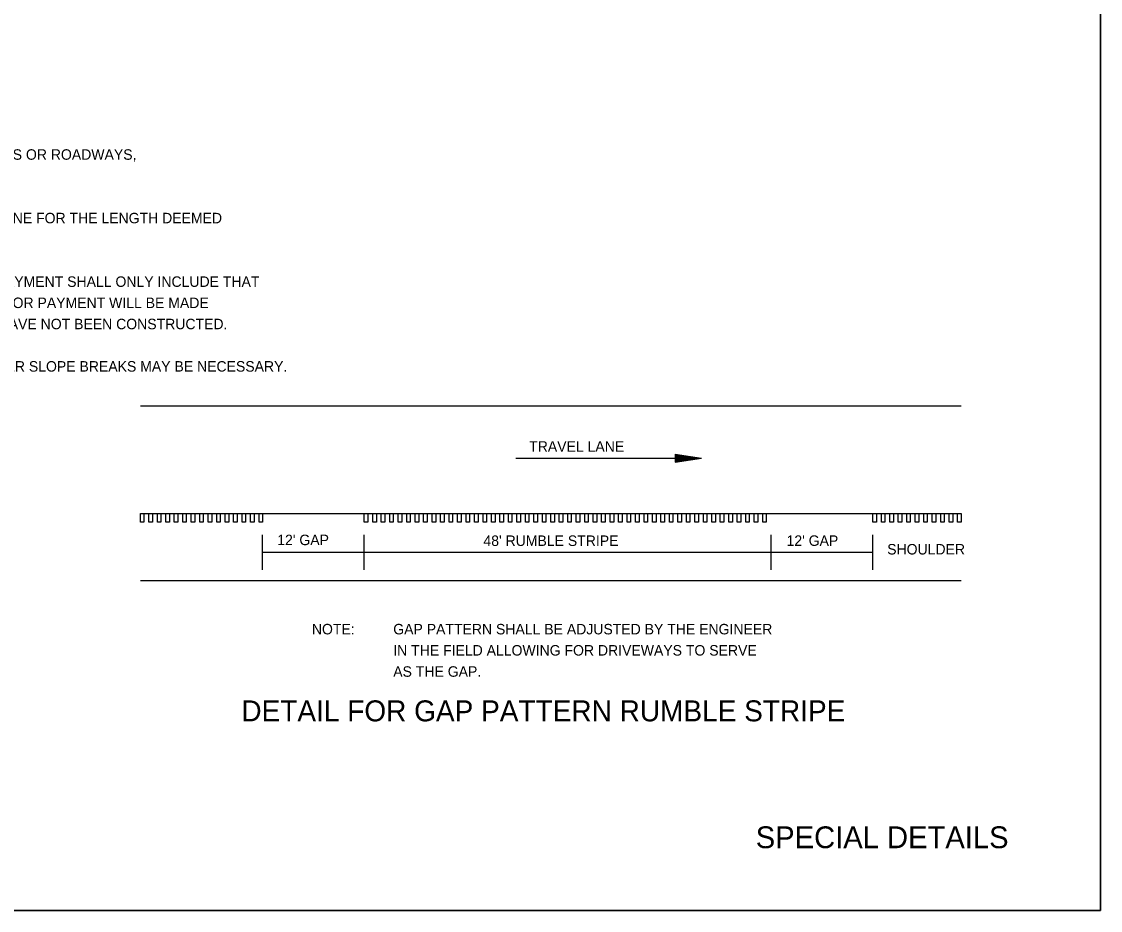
# Model space of a CAD drawing. Extents: x 28704 to 32542, y 50360 to 59122.
# Drawn here: x 29736 to 30404, y 50372 to 50922 of the extents above; entities that cross this region are included whole.
import ezdxf

# ---------------------------------------------------------------- set-up
doc = ezdxf.new("R2010")
doc.units = 0
for name, color, linetype in [('Default', 7, 'Continuous'), ('E_Existing ROW', 7, 'Continuous'), ('R_Alt Surface', 7, 'Continuous'), ('R_Alt Surface Annot', 7, 'Continuous')]:
    doc.layers.add(name, color=color, linetype=linetype)

msp = doc.modelspace()

# ---------------------------------------------------------------- linework, layer by layer
at = {"layer": 'Default'}
for points in [[(28703.96, 51472.36), (30403.96, 51472.36), (30403.96, 50372.36), (28703.96, 50372.36)], [(28703.96, 51472.36), (28703.96, 50372.36), (30403.96, 50372.36), (30403.96, 51472.36)]]:
    msp.add_lwpolyline(points, close=True, dxfattribs=at)
at = {"layer": 'R_Alt Surface'}
for p, q in [((29809.63, 50684.65), (30317.75, 50684.65)), ((30042.08, 50652.23), (30157.03, 50652.23)), ((29809.63, 50618), (30317.75, 50618)), ((29885.28, 50583.19), (29885.28, 50604.81)), ((29948.24, 50583.19), (29948.24, 50604.81)), ((30200.12, 50583.19), (30200.12, 50604.81)), ((30263.09, 50583.19), (30263.09, 50604.81)), ((29885.28, 50594), (29948.24, 50594)), ((29948.24, 50594), (30200.12, 50594)), ((30200.12, 50594), (30263.09, 50594)), ((29809.63, 50576.57), (30317.75, 50576.57))]:
    msp.add_line(p, q, dxfattribs=at)
for points in [[(29809.63, 50612.6), (29809.63, 50618), (29811.81, 50618), (29811.81, 50612.6), (29809.63, 50612.6)], [(29814.87, 50612.6), (29814.87, 50618), (29817.06, 50618), (29817.06, 50612.6), (29814.87, 50612.6)], [(29820.12, 50612.6), (29820.12, 50618), (29822.31, 50618), (29822.31, 50612.6), (29820.12, 50612.6)], [(29825.37, 50612.6), (29825.37, 50618), (29827.55, 50618), (29827.55, 50612.6), (29825.37, 50612.6)], [(29830.62, 50612.6), (29830.62, 50618), (29832.8, 50618), (29832.8, 50612.6), (29830.62, 50612.6)], [(29835.86, 50612.6), (29835.86, 50618), (29838.05, 50618), (29838.05, 50612.6), (29835.86, 50612.6)], [(29841.11, 50612.6), (29841.11, 50618), (29843.3, 50618), (29843.3, 50612.6), (29841.11, 50612.6)], [(29846.36, 50612.6), (29846.36, 50618), (29848.54, 50618), (29848.54, 50612.6), (29846.36, 50612.6)], [(29851.6, 50612.6), (29851.6, 50618), (29853.79, 50618), (29853.79, 50612.6), (29851.6, 50612.6)], [(29856.85, 50612.6), (29856.85, 50618), (29859.04, 50618), (29859.04, 50612.6), (29856.85, 50612.6)], [(29862.1, 50612.6), (29862.1, 50618), (29864.29, 50618), (29864.29, 50612.6), (29862.1, 50612.6)], [(29867.35, 50612.6), (29867.35, 50618), (29869.53, 50618), (29869.53, 50612.6), (29867.35, 50612.6)], [(29872.59, 50612.6), (29872.59, 50618), (29874.78, 50618), (29874.78, 50612.6), (29872.59, 50612.6)], [(29877.84, 50612.6), (29877.84, 50618), (29880.03, 50618), (29880.03, 50612.6), (29877.84, 50612.6)], [(29883.09, 50612.6), (29883.09, 50618), (29885.28, 50618), (29885.28, 50612.6), (29883.09, 50612.6)], [(29948.26, 50612.6), (29948.26, 50618), (29950.45, 50618), (29950.45, 50612.6), (29948.26, 50612.6)], [(29953.51, 50612.6), (29953.51, 50618), (29955.7, 50618), (29955.7, 50612.6), (29953.51, 50612.6)], [(29958.76, 50612.6), (29958.76, 50618), (29960.94, 50618), (29960.94, 50612.6), (29958.76, 50612.6)], [(29964, 50612.6), (29964, 50618), (29966.19, 50618), (29966.19, 50612.6), (29964, 50612.6)], [(29969.25, 50612.6), (29969.25, 50618), (29971.44, 50618), (29971.44, 50612.6), (29969.25, 50612.6)], [(29974.5, 50612.6), (29974.5, 50618), (29976.69, 50618), (29976.69, 50612.6), (29974.5, 50612.6)], [(29979.75, 50612.6), (29979.75, 50618), (29981.93, 50618), (29981.93, 50612.6), (29979.75, 50612.6)], [(29984.99, 50612.6), (29984.99, 50618), (29987.18, 50618), (29987.18, 50612.6), (29984.99, 50612.6)], [(29990.24, 50612.6), (29990.24, 50618), (29992.43, 50618), (29992.43, 50612.6), (29990.24, 50612.6)], [(29995.49, 50612.6), (29995.49, 50618), (29997.67, 50618), (29997.67, 50612.6), (29995.49, 50612.6)], [(30000.74, 50612.6), (30000.74, 50618), (30002.92, 50618), (30002.92, 50612.6), (30000.74, 50612.6)], [(30005.98, 50612.6), (30005.98, 50618), (30008.17, 50618), (30008.17, 50612.6), (30005.98, 50612.6)], [(30011.23, 50612.6), (30011.23, 50618), (30013.42, 50618), (30013.42, 50612.6), (30011.23, 50612.6)], [(30016.48, 50612.6), (30016.48, 50618), (30018.66, 50618), (30018.66, 50612.6), (30016.48, 50612.6)], [(30021.73, 50612.6), (30021.73, 50618), (30023.91, 50618), (30023.91, 50612.6), (30021.73, 50612.6)], [(30026.97, 50612.6), (30026.97, 50618), (30029.16, 50618), (30029.16, 50612.6), (30026.97, 50612.6)], [(30032.22, 50612.6), (30032.22, 50618), (30034.41, 50618), (30034.41, 50612.6), (30032.22, 50612.6)], [(30037.47, 50612.6), (30037.47, 50618), (30039.65, 50618), (30039.65, 50612.6), (30037.47, 50612.6)], [(30042.72, 50612.6), (30042.72, 50618), (30044.9, 50618), (30044.9, 50612.6), (30042.72, 50612.6)], [(30047.96, 50612.6), (30047.96, 50618), (30050.15, 50618), (30050.15, 50612.6), (30047.96, 50612.6)], [(30053.21, 50612.6), (30053.21, 50618), (30055.4, 50618), (30055.4, 50612.6), (30053.21, 50612.6)], [(30058.46, 50612.6), (30058.46, 50618), (30060.64, 50618), (30060.64, 50612.6), (30058.46, 50612.6)], [(30063.7, 50612.6), (30063.7, 50618), (30065.89, 50618), (30065.89, 50612.6), (30063.7, 50612.6)], [(30068.95, 50612.6), (30068.95, 50618), (30071.14, 50618), (30071.14, 50612.6), (30068.95, 50612.6)], [(30074.2, 50612.6), (30074.2, 50618), (30076.39, 50618), (30076.39, 50612.6), (30074.2, 50612.6)], [(30079.45, 50612.6), (30079.45, 50618), (30081.63, 50618), (30081.63, 50612.6), (30079.45, 50612.6)], [(30084.69, 50612.6), (30084.69, 50618), (30086.88, 50618), (30086.88, 50612.6), (30084.69, 50612.6)], [(30089.94, 50612.6), (30089.94, 50618), (30092.13, 50618), (30092.13, 50612.6), (30089.94, 50612.6)], [(30095.19, 50612.6), (30095.19, 50618), (30097.38, 50618), (30097.38, 50612.6), (30095.19, 50612.6)], [(30100.44, 50612.6), (30100.44, 50618), (30102.62, 50618), (30102.62, 50612.6), (30100.44, 50612.6)], [(30105.68, 50612.6), (30105.68, 50618), (30107.87, 50618), (30107.87, 50612.6), (30105.68, 50612.6)], [(30110.93, 50612.6), (30110.93, 50618), (30113.12, 50618), (30113.12, 50612.6), (30110.93, 50612.6)], [(30116.18, 50612.6), (30116.18, 50618), (30118.37, 50618), (30118.37, 50612.6), (30116.18, 50612.6)], [(30121.43, 50612.6), (30121.43, 50618), (30123.61, 50618), (30123.61, 50612.6), (30121.43, 50612.6)], [(30126.67, 50612.6), (30126.67, 50618), (30128.86, 50618), (30128.86, 50612.6), (30126.67, 50612.6)], [(30131.92, 50612.6), (30131.92, 50618), (30134.11, 50618), (30134.11, 50612.6), (30131.92, 50612.6)], [(30137.17, 50612.6), (30137.17, 50618), (30139.35, 50618), (30139.35, 50612.6), (30137.17, 50612.6)], [(30142.42, 50612.6), (30142.42, 50618), (30144.6, 50618), (30144.6, 50612.6), (30142.42, 50612.6)], [(30147.66, 50612.6), (30147.66, 50618), (30149.85, 50618), (30149.85, 50612.6), (30147.66, 50612.6)], [(30152.91, 50612.6), (30152.91, 50618), (30155.1, 50618), (30155.1, 50612.6), (30152.91, 50612.6)], [(30158.16, 50612.6), (30158.16, 50618), (30160.34, 50618), (30160.34, 50612.6), (30158.16, 50612.6)], [(30163.41, 50612.6), (30163.41, 50618), (30165.59, 50618), (30165.59, 50612.6), (30163.41, 50612.6)], [(30168.65, 50612.6), (30168.65, 50618), (30170.84, 50618), (30170.84, 50612.6), (30168.65, 50612.6)], [(30173.9, 50612.6), (30173.9, 50618), (30176.09, 50618), (30176.09, 50612.6), (30173.9, 50612.6)], [(30179.15, 50612.6), (30179.15, 50618), (30181.33, 50618), (30181.33, 50612.6), (30179.15, 50612.6)], [(30184.4, 50612.6), (30184.4, 50618), (30186.58, 50618), (30186.58, 50612.6), (30184.4, 50612.6)], [(30189.64, 50612.6), (30189.64, 50618), (30191.83, 50618), (30191.83, 50612.6), (30189.64, 50612.6)], [(30194.89, 50612.6), (30194.89, 50618), (30197.08, 50618), (30197.08, 50612.6), (30194.89, 50612.6)], [(30263.09, 50612.6), (30263.09, 50618), (30265.27, 50618), (30265.27, 50612.6), (30263.09, 50612.6)], [(30268.34, 50612.6), (30268.34, 50618), (30270.52, 50618), (30270.52, 50612.6), (30268.34, 50612.6)], [(30273.58, 50612.6), (30273.58, 50618), (30275.77, 50618), (30275.77, 50612.6), (30273.58, 50612.6)], [(30278.83, 50612.6), (30278.83, 50618), (30281.02, 50618), (30281.02, 50612.6), (30278.83, 50612.6)], [(30284.08, 50612.6), (30284.08, 50618), (30286.26, 50618), (30286.26, 50612.6), (30284.08, 50612.6)], [(30289.33, 50612.6), (30289.33, 50618), (30291.51, 50618), (30291.51, 50612.6), (30289.33, 50612.6)], [(30294.57, 50612.6), (30294.57, 50618), (30296.76, 50618), (30296.76, 50612.6), (30294.57, 50612.6)], [(30299.82, 50612.6), (30299.82, 50618), (30302.01, 50618), (30302.01, 50612.6), (30299.82, 50612.6)], [(30305.07, 50612.6), (30305.07, 50618), (30307.25, 50618), (30307.25, 50612.6), (30305.07, 50612.6)], [(30310.32, 50612.6), (30310.32, 50618), (30312.5, 50618), (30312.5, 50612.6), (30310.32, 50612.6)], [(30315.56, 50612.6), (30315.56, 50618), (30317.75, 50618), (30317.75, 50612.6), (30315.56, 50612.6)]]:
    msp.add_lwpolyline(points, dxfattribs=at)
at = {"layer": 'R_Alt Surface Annot'}
for p, q in [((30140.77, 50654.74), (30157.03, 50652.23)), ((30140.77, 50654.74), (30140.77, 50649.71)), ((30140.77, 50654.32), (30154.31, 50652.23)), ((30140.77, 50653.89), (30151.51, 50652.23)), ((30140.77, 50653.47), (30148.81, 50652.23)), ((30140.77, 50653.04), (30146.05, 50652.23)), ((30140.77, 50652.62), (30143.34, 50652.23)), ((30140.77, 50649.71), (30157.03, 50652.23)), ((30140.77, 50651.41), (30146.05, 50652.23)), ((30140.77, 50650.56), (30151.51, 50652.23)), ((30140.77, 50650.13), (30154.31, 50652.23)), ((30140.77, 50650.98), (30148.81, 50652.23)), ((30140.77, 50651.83), (30143.34, 50652.23))]:
    msp.add_line(p, q, dxfattribs=at)

# ---------------------------------------------------------------- texts
at = {"layer": 'Default'}
for s, p in [('RUMBLE STRIPES SHALL NOT BE INSTALLED ON BRIDGE DECKS, APPROACH SLABS, INTERSECTING STREETS OR ROADWAYS,', (29267.49, 50836.86)), ('RUMBLE STRIPES SHALL NOT BE INSTALLED ON A PAVED SHOULDER THAT IS USED AS A DECELERATION LANE FOR THE LENGTH DEEMED', (29267.49, 50797.53)), ('RUMBLE STRIPES SHALL BE MEASURED BY THE LINEAR FOOT LONGITUDINALLY ALONG THE SHOULDER.  PAYMENT SHALL ONLY INCLUDE THAT', (29267.49, 50758.2)), ('PORTION OF THE SHOULDER ON WHICH RUMBLE STRIPES HAVE BEEN CONSTRUCTED.  NO MEASUREMENT OR PAYMENT WILL BE MADE', (29267.49, 50745.09)), ('FOR GAPS, DRIVEWAYS, TURNOUTS, OR OTHER PUBLIC ROAD INTERSECTIONS WHERE RUMBLE STRIPES HAVE NOT BEEN CONSTRUCTED.', (29267.49, 50731.98)), ('THE 3/8" DEPTH SHALL GENERALLY APPLY FOR THE ENTIRE 6" LENGTH. SOME VARIATION TO SUIT SHOULDER SLOPE BREAKS MAY BE NECESSARY.', (29267.49, 50705.76))]:
    msp.add_text(s, height=6.48497, dxfattribs=at).set_placement(p)
at = {"layer": 'E_Existing ROW'}
msp.add_text('SPECIAL DETAILS', height=13.5, dxfattribs=at).set_placement((30190.58, 50410.86))
at = {"layer": 'R_Alt Surface'}
for s, height, p in [('TRAVEL LANE', 6.485, (30050.32, 50656.22)), ("12' GAP", 6.485, (29894.35, 50598.38)), ("48' RUMBLE STRIPE", 6.485, (30022, 50597.89)), ("12' GAP", 6.485, (30209.64, 50597.93)), ('SHOULDER', 6.485, (30271.95, 50592.6)), ('NOTE:', 6.485, (29915.79, 50543.16)), ('GAP PATTERN SHALL BE ADJUSTED BY THE ENGINEER', 6.485, (29966.17, 50543.16)), ('IN THE FIELD ALLOWING FOR DRIVEWAYS TO SERVE', 6.485, (29966.17, 50530.05)), ('AS THE GAP.', 6.485, (29966.17, 50516.94)), ('DETAIL FOR GAP PATTERN RUMBLE STRIPE', 12.9699, (29872.13, 50489.35))]:
    msp.add_text(s, height=height, dxfattribs=at).set_placement(p)

doc.saveas('drawing.dxf')
